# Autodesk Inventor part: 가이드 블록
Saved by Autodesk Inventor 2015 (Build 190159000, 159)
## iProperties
Created: 2025-11
Part Number: 가이드 블록
Material: 일반
Document SubType Name: Modeling
Designer: user
Density: 1 g/cm^3
Appearance: 기본값
Author: user
Author: jhkim
Creation Date: 2025-10-31
Sending System: Autodesk Inventor 2026
Preprocessor: ST-DEVELOPER v20.1
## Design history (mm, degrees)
node "가이드 블록1"
node "솔리드1"
node "기준1"
